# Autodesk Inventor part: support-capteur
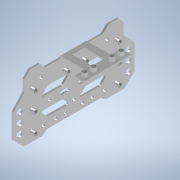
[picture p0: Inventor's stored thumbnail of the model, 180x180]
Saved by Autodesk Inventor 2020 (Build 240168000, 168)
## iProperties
Created: 2022-02
Part Number: support-capteur
Material: Aluminium 6061
Document SubType Name: Modeling
Designer: bruno
Density: 2.94152 g/cm^3
Appearance: Aluminium - Plat
Mass: 19 g
Surface Area: 105.756 cm^2
Volume: 6.45924 cm^3
Author: bruno
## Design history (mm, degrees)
sketch "Esquisse1"
  geometry: L1 (66.232, 46.839)-(46.199, 46.839); L2 (66.23, -52.161)-(46.2, -52.161); L3 (89.845, 25.399)-(89.845, 33.715); L4 (37.796, 38.782)-(37.796, 23.107); L5 (46.199, 46.839)-(37.796, 38.532); L6 (89.845, 25.399)-(85.193, 20.8); L7 (85.193, 20.8)-(85.193, -2.661); L8 (89.845, 33.715)-(85.193, 37.93); L9 (85.193, 37.93)-(76.064, 37.93); L10 (76.064, 37.93)-(66.232, 46.839); L11 (37.796, 23.107)-(40.701, 19.391); L12 (40.701, 19.391)-(40.701, -2.661); L13 (40.701, -2.661)-(50.092, -2.661); L14 (50.092, -2.661)-(85.193, -2.661); L15 (71.331, 18.786)-(71.331, 3.129); L16 (71.016, 19.515)-(66.917, 23.371); L17 (65.232, 7.141)-(65.232, 22.643); L18 (69.631, 2.414)-(65.532, 6.426); L19 (61.89, 7.414)-(61.89, 2.414); L20 (58.89, 7.414)-(58.89, 2.414); L21 (60.39, 17.308)-(60.39, 7.414); L22 (49.764, 19.515)-(53.863, 23.371); L23 (55.548, 7.141)-(55.548, 22.643); L24 (49.449, 18.786)-(49.449, 3.129); L25 (51.148, 2.414)-(55.247, 6.426); C1 r 1.5 at (79.831, 24.339); C2 r 2.5 at (64.046, 41.839); C3 r 2.5 at (56.046, 41.839); C4 r 2.5 at (48.046, 41.839); C5 r 1.5 at (60.39, 17.308); C6 r 1.5 at (44.701, 22.339); C7 r 1.5 at (44.701, 12.339); C8 r 1.5 at (44.701, 4.339); C9 r 1.5 at (60.39, 31.839); C10 r 1.5 at (75.4, 31.839); C11 r 1.5 at (44.89, 31.839); C12 r 1.5 at (75.193, 4.839); C13 r 1.5 at (50.831, -2.661); A1 r 1.5 centre (60.39, 7.414) between (61.89, 7.414) and (58.89, 7.414); A2 r 1 centre (70.331, 3.129) between (69.631, 2.414) and (71.331, 3.129); A3 r 1 centre (66.232, 7.141) between (65.232, 7.141) and (65.532, 6.426); A4 r 1 centre (66.232, 22.643) between (66.917, 23.371) and (65.232, 22.643); A5 r 1 centre (70.331, 18.786) between (71.331, 18.786) and (71.016, 19.515); A6 r 1.5 centre (60.39, 2.414) between (58.89, 2.414) and (61.89, 2.414); A7 r 1 centre (54.548, 22.643) between (55.548, 22.643) and (53.863, 23.371); A8 r 1 centre (50.449, 18.786) between (49.764, 19.515) and (49.449, 18.786); A9 r 1 centre (54.548, 7.141) between (55.247, 6.426) and (55.548, 7.141); A10 r 1 centre (50.449, 3.129) between (49.449, 3.129) and (51.148, 2.414); 3 further points
  constraints: 50 end point, 23 centre point, 20 point on circle, 12 symmetric about line, 10 tangent, 6 vertical, 3 horizontal, 3 parallel, 2 equal radius, 2 point on line, 1 perpendicular, 4 other
  dimensions: "d5" = 99 distance between parallel lines of L2 L1; "d8" = 52.04902 distance between parallel lines of L3 L4; "d16" = 49.5 distance between parallel lines of L1 L13; "d17" = 1 radius of A2 (derived); "d19" = 1 radius of A5 (derived); "d20" = 5 diameter of C2; "d21" = 5 diameter of C3; "d22" = 5 diameter of C4; "d23" = 3 dimension on C4 C3; "d24" = 8 distance of C2.centre C3.centre; "d25" = 5 distance from line of C2.centre L1; "d26" = 5 distance from line of L1 C3.centre; "d27" = 7.5 dimension on C4 L1; "d28" = 3 diameter of C10; "d29" = 3 diameter of C9; "d30" = 3 diameter of C11; "d31" = 15 distance from line of L1 C9.centre; "d32" = 15 distance from line of L1 C11.centre; "d33" = 15 distance from line of L1 C10.centre; "d34" = 3 diameter of C6; "d35" = 3 diameter of C7; "d36" = 3 diameter of C8; "d37" = 24.5 distance from line of C6.centre L1; "d38" = 4 distance from line of L12 C6.centre; "d39" = 4 distance from line of L12 C7.centre; "d40" = 4 distance from line of L12 C8.centre; "d41" = 10 distance of C7.centre C6.centre; "d42" = 8 distance of C8.centre C7.centre; "d43" = 3 diameter of C1; "d44" = 10 distance from line of C12.centre L7; "d45" = 3 diameter of C12; "d46" = 27 vertical distance of C12.centre C10.centre; "d47" = 3 diameter of C5; "d48" = 3 diameter of A6; "d49" = 3 diameter of A1; "d50" = 5 distance of A6.centre L21.end; "d52" = 3 diameter of C13; "d103" = 34.5 distance from line of L14 C10.centre (derived); "d104" = 27 distance from line of L14 C1.centre; "d105" = 29 horizontal distance of C13.centre C1.centre
extrude "Extrusion1" new body sketch "Esquisse1" distance "d53" = 1.5; taper "d54" = 0 deg
sketch "Esquisse2"
  geometry: C1 r 1.5 at (-31.839, 75.4) reference; C2 r 1.5 at (-31.839, 60.39) reference; C3 r 1.5 at (-31.839, 44.89) reference; C4 r 1.5 at (-4.839, 75.193) reference; C5 r 1.5 at (10.161, 75.193) reference; C6 r 1.5 at (37.161, 75.4) reference; C7 r 1.5 at (37.161, 60.39) reference; C8 r 1.5 at (37.161, 44.89) reference; C9 r 2 at (-31.839, 75.4); C10 r 1.5 at (-31.839, 60.39) reference; C11 r 2 at (-31.839, 60.39); C12 r 1.5 at (-31.839, 44.89) reference; C13 r 2 at (-31.839, 44.89); C14 r 1.5 at (-4.839, 75.193) reference; C15 r 2 at (-4.839, 75.193); 1 further point
  constraints: 4 centre point, 4 coincident
  dimensions: "d55" = 4 diameter of C9; "d56" = 4 diameter of C11; "d57" = 4 diameter of C13; "d58" = 4 diameter of C15
extrude "Extrusion2" join sketch "Esquisse2" distance "d59" = 3; taper "d60" = 0 deg
feature "Filetage1" dims "d61" = 4.5, "d62" = 0
feature "Filetage2" dims "d63" = 4.5, "d64" = 0
feature "Filetage3" dims "d65" = 4.5, "d66" = 0
feature "Filetage4" dims "d67" = 4.5, "d68" = 0
mirror "Symétrie2"
sketch "Esquisse3"
  geometry: L1 (0, 0)-(0, 46.922) reference; L2 (1.5, 0)-(1.5, 46.922) reference; L3 (0, 1.409)-(0, 45.513) reference; L4 (0, 12.961)-(20.5, 12.961); L5 (21, 12.961)-(21, 27.961); L6 (20.5, 33.961)-(0, 33.961); L7 (0, 33.961)-(0, 12.961); L8 (21.5, 4.461)-(28.5, 4.461); L9 (29, 4.961)-(29, 41.961); L10 (28.5, 42.461)-(21.5, 42.461); L11 (21, 12.461)-(21, 4.961); L12 (1.5, 1.409)-(1.5, 45.513) reference; L13 (1.5, 23.461)-(-9.009, 23.461); L14 (5.5, 18.461)-(20.5, 18.461); L15 (21, 18.961)-(21, 28.461); L16 (20.5, 28.461)-(5.5, 28.461); L17 (5, 27.961)-(5, 18.961); L18 (21, 41.961)-(21, 34.461); C1 r 1.5 at (25, 8.461); C2 r 1.5 at (25, 15.961); C3 r 1.5 at (25, 30.961); C4 r 1.5 at (25, 38.461); A1 r 0.5 centre (20.5, 12.461) between (21, 12.461) and (20.5, 12.961); A2 r 0.5 centre (5.5, 18.961) between (5, 18.961) and (5.5, 18.461); A3 r 0.5 centre (20.5, 18.961) between (20.5, 18.461) and (21, 18.961); A4 r 0.5 centre (20.5, 27.961) between (21, 27.961) and (20.5, 28.461); A5 r 0.5 centre (5.5, 27.961) between (5.5, 28.461) and (5, 27.961); A6 r 0.5 centre (20.5, 34.461) between (20.5, 33.961) and (21, 34.461); A7 r 0.5 centre (21.5, 41.961) between (21.5, 42.461) and (21, 41.961); A8 r 0.5 centre (28.5, 41.961) between (29, 41.961) and (28.5, 42.461); A9 r 0.5 centre (28.5, 4.961) between (28.5, 4.461) and (29, 4.961); A10 r 0.5 centre (21.5, 4.961) between (21, 4.961) and (21.5, 4.461); 10 further points
  constraints: 28 end point, 20 point on circle, 20 tangent, 18 point on line, 14 centre point, 8 equal radius, 6 parallel, 4 horizontal, 3 perpendicular, 2 symmetric about line, 1 midpoint, 1 vertical, 2 other
  dimensions: "d69" = 21 distance of L6.end point (21, 33.961); "d70" = 21 distance of point (21, 33.961) L5.start; "d71" = 8 distance of point (21, 42.461) point (29, 42.461); "d72" = 38 distance of point (29, 42.461) point (29, 4.461); "d73" = 10.5 distance between parallel lines of L6 L13; "d74" = 19 distance between parallel lines of L8 L13; "d75" = 10 distance between parallel lines of L16 L14; "d76" = 16 distance of point (5, 18.461) point (21, 18.461); "d77" = 5 distance between parallel lines of L13 L14; "d78" = 5 distance between parallel lines of L7 L17; "d79" = 0.5 radius of A1; "d80" = 0.5 radius of A6 (derived); "d81" = 3 diameter of C1; "d82" = 3 diameter of C2; "d83" = 7.5 distance from line of C2.centre L13; "d84" = 15 distance from line of L13 C1.centre
extrude "Extrusion3" join sketch "Esquisse3" distance "d85" = 1.5; taper "d86" = 0 deg
fillet "Congé1" dims "d87" = 1
sketch "Esquisse4"
  geometry: C1 r 1.5 at (25, 8.461) reference; C2 r 1.5 at (25, 15.961) reference; C3 r 1.5 at (25, 30.961) reference; C4 r 1.5 at (25, 38.461) reference; C5 r 2 at (25, 8.461); C6 r 1.5 at (25, 15.961) reference; C7 r 2 at (25, 15.961); C8 r 1.5 at (25, 30.961) reference; C9 r 2 at (25, 30.961); C10 r 2 at (25, 38.461); 1 further point
  constraints: 4 centre point, 4 coincident
  dimensions: "d88" = 4 diameter of C5; "d89" = 4 diameter of C7; "d90" = 4 diameter of C9; "d91" = 4 diameter of C10
extrude "Extrusion4" join sketch "Esquisse4" distance "d92" = 3; taper "d93" = 0 deg
feature "Filetage5" dims "d94" = 4.5, "d95" = 0
feature "Filetage6" dims "d96" = 4.5, "d97" = 0
feature "Filetage7" dims "d98" = 4.5, "d99" = 0
feature "Filetage8" dims "d100" = 4.5, "d101" = 0
node "Solide1"
